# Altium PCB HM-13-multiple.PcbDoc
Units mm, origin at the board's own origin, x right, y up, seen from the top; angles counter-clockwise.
Board outline 81.48 x 88.14 mm, 2 copper layers (Top Layer, Bottom Layer); 96 components, 8 nets, 330 pads, 208 vias.
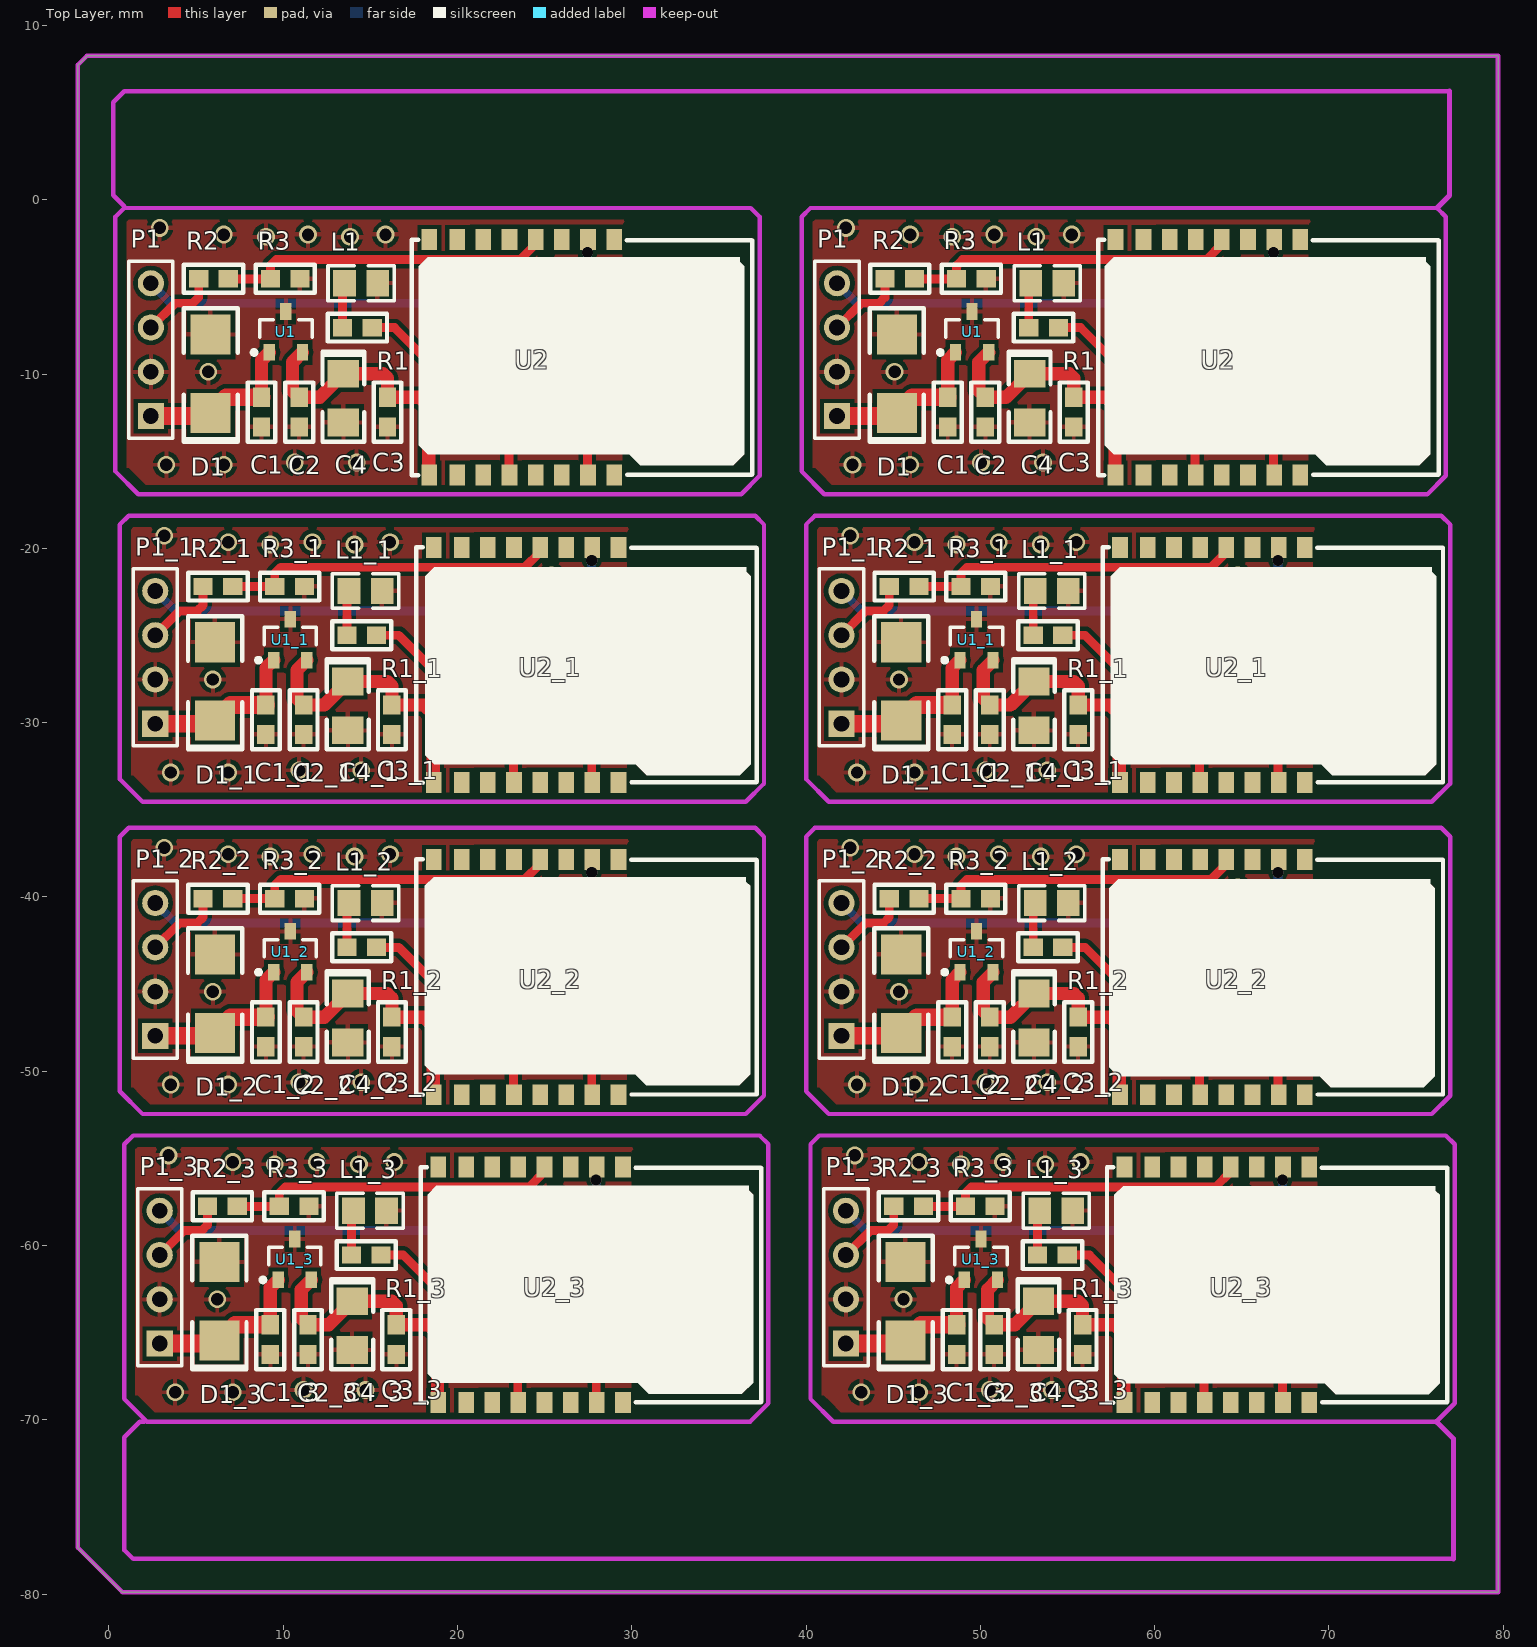
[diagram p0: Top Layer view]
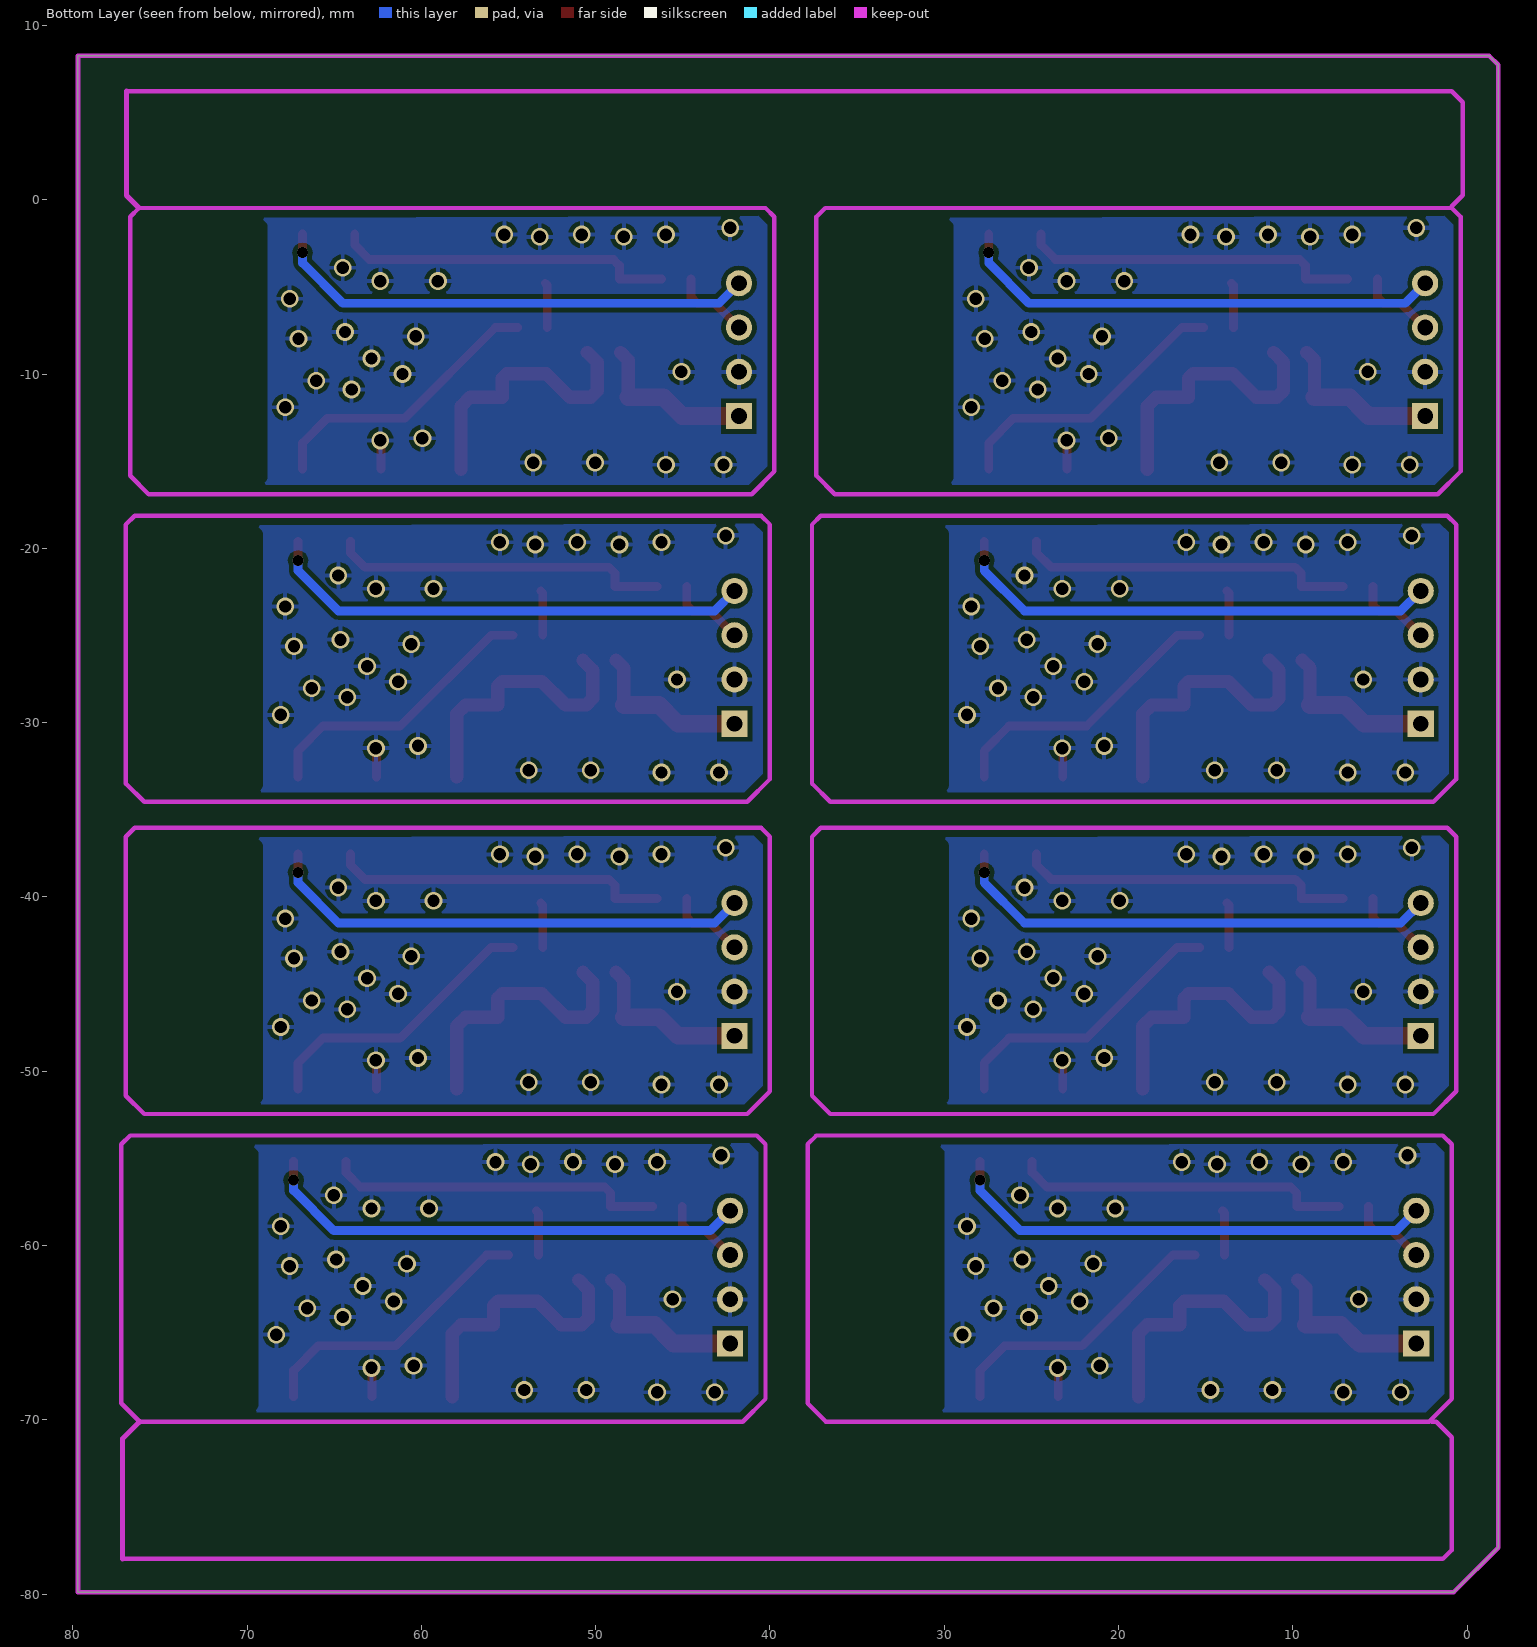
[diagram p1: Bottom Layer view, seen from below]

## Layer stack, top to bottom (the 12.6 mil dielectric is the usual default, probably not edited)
Top Solder: solder mask 0.0102, Solder Resist, Dk 3.5
Top Layer: signal copper 0.0356
Dielectric 1: dielectric 0.32, FR-4, Dk 4.8
Bottom Layer: signal copper 0.0356
Bottom Solder: solder mask 0.0102, Solder Resist, Dk 3.5

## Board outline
-1.778,5.842 -1.778,7.747 -1.27,8.255 79.705,8.255 79.705,-79.883 0.762,-79.883 -1.778,-77.343

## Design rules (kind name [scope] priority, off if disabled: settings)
Clearance [All] p1: gap=0.254
PolygonConnect [All] p1: connectstyle=Relief reliefconductorwidth=0.254 reliefentries=4 polygonreliefangle="90 Angle" airgapwidth=0.254
RoutingVias [All] p1: holewidth=0.711 width=1.016 viastyle="Through Hole" minholewidth=0.635 minwidth=0.381 maxholewidth=0.711 maxwidth=1.016
SolderMaskExpansion [All] p1: expansion=0.102
Width [All] p1: maxlimit=1.016 minlimit=0.254 preferedwidth=0.508
30 further rules are at their usual default settings.

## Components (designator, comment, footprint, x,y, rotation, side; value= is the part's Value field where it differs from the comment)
C1 "1uF" 0603 8.767,-12.185 r90 top
C1 "1uF" 0603 48.137,-12.185 r90 top
C1_1 "1uF" 0603 48.391,-29.838 r90 top (schematic designator C1)
C1_1 "1uF" 0603 9.021,-29.838 r90 top (schematic designator C1)
C1_2 "1uF" 0603 48.391,-47.745 r90 top (schematic designator C1)
C1_2 "1uF" 0603 9.021,-47.745 r90 top (schematic designator C1)
C1_3 "1uF" 0603 48.645,-65.398 r90 top (schematic designator C1)
C1_3 "1uF" 0603 9.275,-65.398 r90 top (schematic designator C1)
C2 "1uF" 0603 10.926,-12.185 r90 top
C2 "1uF" 0603 50.296,-12.185 r90 top
C2_1 "1uF" 0603 50.55,-29.838 r90 top (schematic designator C2)
C2_1 "1uF" 0603 11.18,-29.838 r90 top (schematic designator C2)
C2_2 "1uF" 0603 50.55,-47.745 r90 top (schematic designator C2)
C2_2 "1uF" 0603 11.18,-47.745 r90 top (schematic designator C2)
C2_3 "1uF" 0603 50.804,-65.398 r90 top (schematic designator C2)
C2_3 "1uF" 0603 11.434,-65.398 r90 top (schematic designator C2)
C3 "0.1uF" 0603 15.996,-12.185 r90 top
C3 "0.1uF" 0603 55.366,-12.185 r90 top
C3_1 "0.1uF" 0603 55.62,-29.838 r90 top (schematic designator C3)
C3_1 "0.1uF" 0603 16.25,-29.838 r90 top (schematic designator C3)
C3_2 "0.1uF" 0603 55.62,-47.745 r90 top (schematic designator C3)
C3_2 "0.1uF" 0603 16.25,-47.745 r90 top (schematic designator C3)
C3_3 "0.1uF" 0603 55.874,-65.398 r90 top (schematic designator C3)
C3_3 "0.1uF" 0603 16.504,-65.398 r90 top (schematic designator C3)
C4 "10uF/16V" 1206 13.456,-11.395 r270 top
C4 "10uF/16V" 1206 52.826,-11.395 r270 top
C4_1 "10uF/16V" 1206 53.08,-29.048 r270 top (schematic designator C4)
C4_1 "10uF/16V" 1206 13.71,-29.048 r270 top (schematic designator C4)
C4_2 "10uF/16V" 1206 53.08,-46.955 r270 top (schematic designator C4)
C4_2 "10uF/16V" 1206 13.71,-46.955 r270 top (schematic designator C4)
C4_3 "10uF/16V" 1206 53.334,-64.608 r270 top (schematic designator C4)
C4_3 "10uF/16V" 1206 13.964,-64.608 r270 top (schematic designator C4)
D1 "TVS" DO214-AC 5.836,-9.985 r270 top
D1 "TVS" DO214-AC 45.206,-9.985 r270 top
D1_1 "TVS" DO214-AC 45.46,-27.638 r270 top (schematic designator D1)
D1_1 "TVS" DO214-AC 6.09,-27.638 r270 top (schematic designator D1)
D1_2 "TVS" DO214-AC 45.46,-45.545 r270 top (schematic designator D1)
D1_2 "TVS" DO214-AC 6.09,-45.545 r270 top (schematic designator D1)
D1_3 "TVS" DO214-AC 45.714,-63.198 r270 top (schematic designator D1)
D1_3 "TVS" DO214-AC 6.344,-63.198 r270 top (schematic designator D1)
L1 "LED" 0805 14.472,-4.791 r0 top
L1 "LED" 0805 53.842,-4.791 r0 top
L1_1 "LED" 0805 54.096,-22.444 r0 top (schematic designator L1)
L1_1 "LED" 0805 14.726,-22.444 r0 top (schematic designator L1)
L1_2 "LED" 0805 54.096,-40.351 r0 top (schematic designator L1)
L1_2 "LED" 0805 14.726,-40.351 r0 top (schematic designator L1)
L1_3 "LED" 0805 54.35,-58.004 r0 top (schematic designator L1)
L1_3 "LED" 0805 14.98,-58.004 r0 top (schematic designator L1)
P1 "Header 4" HDR1X4 2.407,-12.411 r90 top
P1 "Header 4" HDR1X4 41.777,-12.411 r90 top
P1_1 "Header 4" HDR1X4 42.031,-30.064 r90 top (schematic designator P1)
P1_1 "Header 4" HDR1X4 2.661,-30.064 r90 top (schematic designator P1)
P1_2 "Header 4" HDR1X4 42.031,-47.971 r90 top (schematic designator P1)
P1_2 "Header 4" HDR1X4 2.661,-47.971 r90 top (schematic designator P1)
P1_3 "Header 4" HDR1X4 42.285,-65.624 r90 top (schematic designator P1)
P1_3 "Header 4" HDR1X4 2.915,-65.624 r90 top (schematic designator P1)
R1 "470" 0603 14.257,-7.321 r180 top
R1 "470" 0603 53.627,-7.321 r180 top
R1_1 "470" 0603 53.881,-24.974 r180 top (schematic designator R1)
R1_1 "470" 0603 14.511,-24.974 r180 top (schematic designator R1)
R1_2 "470" 0603 53.881,-42.881 r180 top (schematic designator R1)
R1_2 "470" 0603 14.511,-42.881 r180 top (schematic designator R1)
R1_3 "470" 0603 54.135,-60.534 r180 top (schematic designator R1)
R1_3 "470" 0603 14.765,-60.534 r180 top (schematic designator R1)
R2 "2.2K" 0603 6.002,-4.527 r180 top
R2 "2.2K" 0603 45.372,-4.527 r180 top
R2_1 "2.2K" 0603 45.626,-22.18 r180 top (schematic designator R2)
R2_1 "2.2K" 0603 6.256,-22.18 r180 top (schematic designator R2)
R2_2 "2.2K" 0603 45.626,-40.087 r180 top (schematic designator R2)
R2_2 "2.2K" 0603 6.256,-40.087 r180 top (schematic designator R2)
R2_3 "2.2K" 0603 45.88,-57.74 r180 top (schematic designator R2)
R2_3 "2.2K" 0603 6.51,-57.74 r180 top (schematic designator R2)
R3 "4.7K" 0603 10.115,-4.527 r180 top
R3 "4.7K" 0603 49.485,-4.527 r180 top
R3_1 "4.7K" 0603 49.739,-22.18 r180 top (schematic designator R3)
R3_1 "4.7K" 0603 10.369,-22.18 r180 top (schematic designator R3)
R3_2 "4.7K" 0603 49.739,-40.087 r180 top (schematic designator R3)
R3_2 "4.7K" 0603 10.369,-40.087 r180 top (schematic designator R3)
R3_3 "4.7K" 0603 49.993,-57.74 r180 top (schematic designator R3)
R3_3 "4.7K" 0603 10.623,-57.74 r180 top (schematic designator R3)
U1 "AP7313" AP7313-33SAG-7 10.154,-7.585 r90 top
U1 "AP7313" AP7313-33SAG-7 49.524,-7.585 r90 top
U1_1 "AP7313" AP7313-33SAG-7 49.778,-25.238 r90 top (schematic designator U1)
U1_1 "AP7313" AP7313-33SAG-7 10.408,-25.238 r90 top (schematic designator U1)
U1_2 "AP7313" AP7313-33SAG-7 49.778,-43.145 r90 top (schematic designator U1)
U1_2 "AP7313" AP7313-33SAG-7 10.408,-43.145 r90 top (schematic designator U1)
U1_3 "AP7313" AP7313-33SAG-7 50.032,-60.798 r90 top (schematic designator U1)
U1_3 "AP7313" AP7313-33SAG-7 10.662,-60.798 r90 top (schematic designator U1)
U2 "HM-13" HM-13 17.387,-2.286 r270 top
U2 "HM-13" HM-13 56.757,-2.286 r270 top
U2_1 "HM-13" HM-13 57.011,-19.939 r270 top (schematic designator U2)
U2_1 "HM-13" HM-13 17.641,-19.939 r270 top (schematic designator U2)
U2_2 "HM-13" HM-13 57.011,-37.846 r270 top (schematic designator U2)
U2_2 "HM-13" HM-13 17.641,-37.846 r270 top (schematic designator U2)
U2_3 "HM-13" HM-13 57.265,-55.499 r270 top (schematic designator U2)
U2_3 "HM-13" HM-13 17.895,-55.499 r270 top (schematic designator U2)

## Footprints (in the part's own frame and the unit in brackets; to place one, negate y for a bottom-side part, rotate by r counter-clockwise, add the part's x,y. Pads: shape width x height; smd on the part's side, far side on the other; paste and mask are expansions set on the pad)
0603 [mm]
  rect 1.1x1 smd: 1(-0.85,0.01) 2(0.85,0.01)
  silkscreen extent -1.7,-0.79 1.7,0.81
0805 [mm]
  rect 1.3x1.5 smd: 1(-0.95,0) 2(0.95,0)
  silkscreen extent -1.9,-1 1.9,1
1206 [mm]
  rect 1.6x1.8 smd: 1(-1.41,0) 2(1.39,0)
  silkscreen extent -2.68,-1.2 2.49,1.2
AP7313-33SAG-7 [mm] "SOT23, 3-Leads, Body 2.90x2.40mm, Pitch 0.95mm, IPC Medium Density"
  rect 0.95x0.65 smd: 1(-1.175,0.95) 2(-1.175,-0.95) 3(1.175,0)
  silkscreen extent -1.3,-1.5 0.7,1.95
DO214-AC [mm]
  rect 2.3x2.3 smd: 1(-2.25,0) 2(2.25,0)
  silkscreen extent -3.75,-1.55 3.9,1.55
HDR1X4 [mm] "Connector; Header; 4 Position"
  rect 1.5x1.5 hole 0.9: 1(0,0)
  round 1.5 hole 0.9: 2(2.54,0) 3(5.08,0) 4(7.62,0)
  silkscreen extent -1.27,-1.27 8.89,1.27
HM-13 [mm]
  rect 1.2x0.9 smd: 1(0,11.6) 2(0,10.1) 3(0,8.6) 4(0,7.1) 5(0,5.6) 6(0,4.1) 7(0,2.6) 8(0,1) 9(13.5,1) 10(13.5,2.6) 11(13.5,4.1) 12(13.5,5.6) 13(13.5,7.1) 14(13.5,8.6) 15(13.5,10.1) 16(13.5,11.6)
  silkscreen extent 0,0 13.51,19.53

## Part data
C1 C1 C1_1 C1_1 C1_2 C1_2 C1_3 C1_3 C2 C2 C2_1 C2_1 C2_2 C2_2 C2_3 C2_3 C3 C3 C3_1 C3_1 C3_2 C3_2 C3_3 C3_3: library part Cap1, "ceramic"
C4 C4 C4_1 C4_1 C4_2 C4_2 C4_3 C4_3: library part Cap3, "aluminum"
D1 D1 D1_1 D1_1 D1_2 D1_2 D1_3 D1_3: library part 6V8A-TVS
P1 P1 P1_1 P1_1 P1_2 P1_2 P1_3 P1_3: "Header, 4-Pin"
R1 R1 R1_1 R1_1 R1_2 R1_2 R1_3 R1_3 R2 R2 R2_1 R2_1 R2_2 R2_2 R2_3 R2_3 R3 R3 R3_1 R3_1 R3_2 R3_2 R3_3 R3_3: library part Res
U1 U1 U1_1 U1_1 U1_2 U1_2 U1_3 U1_3: library part AP7313-33SAG-7

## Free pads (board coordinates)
  round 2.032 on Keep-Out: 2(3.81,3.937) 4(74.371,-76.073)

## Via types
v1: diameter 1.016, hole 0.711, Top Layer to Bottom Layer, 200 vias
v2: diameter 0.635, hole 0.635, Top Layer to Bottom Layer, 8 vias

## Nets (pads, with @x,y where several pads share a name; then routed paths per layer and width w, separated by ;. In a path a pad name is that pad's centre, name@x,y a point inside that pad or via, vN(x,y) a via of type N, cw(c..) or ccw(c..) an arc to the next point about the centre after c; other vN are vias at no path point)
3.3V: C2.2@10.916,-11.335 C3.2@15.986,-11.335 C4.1@13.456,-9.985 U1.2@11.104,-8.76 U2.9@18.387,-15.786 | length 16
  Top Layer w0.762: U1.2@11.104,-8.76 10.535,-9.329 10.535,-10.954 10.916,-11.335 12.106,-11.335 13.456,-9.985 15.729,-9.985 15.986,-10.242 15.986,-11.335 17.841,-11.335 18.35,-11.844 U2.9@18.35,-15.459
5V: C1.2@8.757,-11.335 D1.2@5.836,-12.234 P1.1@2.407,-12.411 U1.1@9.204,-8.76 | length 9.6
  Top Layer w0.762: C1.2@8.757,-11.335 8.757,-9.207 U1.1@9.204,-8.76
  Top Layer w1.016: P1.1@2.407,-12.411 5.66,-12.411 5.836,-12.234 6.736,-11.335 C1.2@8.757,-11.335
GND: C1.1@8.757,-13.035 C2.1@10.916,-13.035 C3.1@15.986,-13.035 C4.2@13.456,-12.785 D1.1@5.836,-7.735 L1.2@15.422,-4.791 P1.2@2.407,-9.871 R3.1@10.965,-4.537 U1.3@10.154,-6.41 U2.12@22.987,-15.786 | length 1.7
  Top Layer w0.508: U2.12@22.95,-15.459 22.95,-13.839 v1(22.981,-13.808)
  other v1: 3.296,-15.205 6.598,-15.205 10.662,-15.078 14.218,-15.078 20.568,-13.681 28.442,-11.903 24.632,-10.887 26.664,-10.379 21.711,-9.998 5.709,-9.871 23.489,-9.109 27.68,-7.966 20.949,-7.839 25.013,-7.585 28.188,-5.68 19.679,-4.664 22.981,-4.664 25.14,-3.902 9.011,-2.124 13.837,-2.124 6.598,-1.997 11.424,-1.997 15.869,-1.997 2.915,-1.616
NetL1_1: L1.1@13.522,-4.791 R1.2@13.407,-7.331 | length 2.6
  Top Layer w0.508: R1.2@13.407,-7.331 13.407,-4.906 L1.1@13.522,-4.791
NetR1_1: R1.1@15.107,-7.331 U2.15@27.487,-15.786 | length 16.6
  Top Layer w0.508: R1.1@15.107,-7.331 16.377,-7.331 21.584,-12.538 26.029,-12.538 27.45,-13.959 U2.15@27.45,-15.459
NetR2_1: R2.1@6.852,-4.537 R3.2@9.265,-4.537 U2.4@24.487,-2.286 | length 19.5
  Top Layer w0.508: R2.1@6.852,-4.537 9.265,-4.537 9.265,-3.775 9.611,-3.429 23.612,-3.429 24.45,-2.591 U2.4@24.45,-1.959
RX: P1.3@2.407,-7.331 R2.2@5.152,-4.537 | length 4.5
  Top Layer w0.508: P1.3@2.407,-7.331 3.804,-5.934 4.82,-5.934 5.152,-5.602 R2.2@5.152,-4.537
TX: P1.4@2.407,-4.791 U2.2@27.487,-2.286 | length 28.1
  Top Layer w0.508: v2(27.45,-3.037) U2.2@27.45,-1.959
  Bottom Layer w0.508: P1.4@2.407,-4.791 3.55,-5.934 25.14,-5.934 27.45,-3.624 v2(27.45,-3.037)
pads on no net: C1.1@48.127,-13.035 C1.2@48.127,-11.335 C1_1.1 C1_1.2 C1_2.1 C1_2.2 C1_3.1 C1_3.2 C2.1@50.286,-13.035 C2.2@50.286,-11.335 C2_1.1 C2_1.2 C2_2.1 C2_2.2 C2_3.1 C2_3.2 C3.1@55.356,-13.035 C3.2@55.356,-11.335 C3_1.1 C3_1.2 C3_2.1 C3_2.2 C3_3.1 C3_3.2 C4.1@52.826,-9.985 C4.2@52.826,-12.785 C4_1.1 C4_1.2 C4_2.1 C4_2.2 C4_3.1 C4_3.2 D1.1@45.206,-7.735 D1.2@45.206,-12.234 D1_1.1 D1_1.2 D1_2.1 D1_2.2 D1_3.1 D1_3.2 L1.1@52.892,-4.791 L1.2@54.792,-4.791 L1_1.1 L1_1.2 L1_2.1 L1_2.2 L1_3.1 L1_3.2 P1.1@41.777,-12.411 P1.2@41.777,-9.871 P1.3@41.777,-7.331 P1.4@41.777,-4.791 P1_1.1 P1_1.2 P1_1.3 P1_1.4 P1_2.1 P1_2.2 P1_2.3 P1_2.4 P1_3.1 P1_3.2 P1_3.3 P1_3.4 R1.1@54.477,-7.331 R1.2@52.777,-7.331 R1_1.1 R1_1.2 R1_2.1 R1_2.2 R1_3.1 R1_3.2 R2.1@46.222,-4.537 R2.2@44.522,-4.537 R2_1.1 R2_1.2 R2_2.1 R2_2.2 R2_3.1 R2_3.2 R3.1@50.335,-4.537 R3.2@48.635,-4.537 R3_1.1 R3_1.2 R3_2.1 R3_2.2 R3_3.1 R3_3.2 U1.1@48.574,-8.76 U1.2@50.474,-8.76 U1.3@49.524,-6.41 U1_1.1 U1_1.2 U1_1.3 U1_2.1 U1_2.2 U1_2.3 U1_3.1 U1_3.2 U1_3.3 U2.1 U2.2@66.857,-2.286 U2.3 U2.4@63.857,-2.286 U2.5 U2.6 U2.7 U2.8 U2.9@57.757,-15.786 U2.10 U2.11 U2.12@62.357,-15.786 U2.13 U2.14 U2.15@66.857,-15.786 U2.16 U2_1.1 U2_1.2 U2_1.3 U2_1.4 U2_1.5 U2_1.6 U2_1.7 U2_1.8 U2_1.9 U2_1.10 U2_1.11 U2_1.12 U2_1.13 U2_1.14 U2_1.15 U2_1.16 U2_2.1 U2_2.2 U2_2.3 U2_2.4 U2_2.5 U2_2.6 U2_2.7 U2_2.8 U2_2.9 U2_2.10 U2_2.11 U2_2.12 U2_2.13 U2_2.14 U2_2.15 U2_2.16 U2_3.1 U2_3.2 U2_3.3 U2_3.4 U2_3.5 U2_3.6 U2_3.7 U2_3.8 U2_3.9 U2_3.10 U2_3.11 U2_3.12 U2_3.13 U2_3.14 U2_3.15 U2_3.16
copper on no net: | length 689.7
  Top Layer w0.508: 2.661,-42.891 4.058,-41.494 5.074,-41.494 5.406,-41.162 5.406,-40.097 ; 2.661,-24.984 4.058,-23.587 5.074,-23.587 5.406,-23.255 5.406,-22.19 ; 2.915,-60.544 4.312,-59.147 5.328,-59.147 5.66,-58.815 5.66,-57.75 ; 7.106,-40.097 9.519,-40.097 9.519,-39.335 9.865,-38.989 23.866,-38.989 24.704,-38.151 24.704,-37.519 ; 7.106,-22.19 9.519,-22.19 9.519,-21.428 9.865,-21.082 23.866,-21.082 24.704,-20.244 24.704,-19.612 ; 7.36,-57.75 9.773,-57.75 9.773,-56.988 10.119,-56.642 24.12,-56.642 24.958,-55.804 24.958,-55.172 ; 13.661,-42.891 13.661,-40.466 13.776,-40.351 ; 13.661,-24.984 13.661,-22.559 13.776,-22.444 ; 13.915,-60.544 13.915,-58.119 14.03,-58.004 ; 15.361,-42.891 16.631,-42.891 21.838,-48.098 26.283,-48.098 27.704,-49.519 27.704,-51.019 ; 15.361,-24.984 16.631,-24.984 21.838,-30.191 26.283,-30.191 27.704,-31.612 27.704,-33.112 ; 15.615,-60.544 16.885,-60.544 22.092,-65.751 26.537,-65.751 27.958,-67.172 27.958,-68.672 ; 23.204,-51.019 23.204,-49.399 v1(23.235,-49.368) ; 23.204,-33.112 23.204,-31.492 v1(23.235,-31.461) ; 23.458,-68.672 23.458,-67.052 v1(23.489,-67.021) ; v2(27.704,-38.597) 27.704,-37.519 ; v2(27.704,-20.69) 27.704,-19.612 ; v2(27.958,-56.25) 27.958,-55.172 ; 41.777,-7.331 43.174,-5.934 44.19,-5.934 44.522,-5.602 44.522,-4.537 ; 42.031,-42.891 43.428,-41.494 44.444,-41.494 44.776,-41.162 44.776,-40.097 ; 42.031,-24.984 43.428,-23.587 44.444,-23.587 44.776,-23.255 44.776,-22.19 ; 42.285,-60.544 43.682,-59.147 44.698,-59.147 45.03,-58.815 45.03,-57.75 ; 46.222,-4.537 48.635,-4.537 48.635,-3.775 48.981,-3.429 62.982,-3.429 63.82,-2.591 63.82,-1.959 ; 46.476,-40.097 48.889,-40.097 48.889,-39.335 49.235,-38.989 63.236,-38.989 64.074,-38.151 64.074,-37.519 ; 46.476,-22.19 48.889,-22.19 48.889,-21.428 49.235,-21.082 63.236,-21.082 64.074,-20.244 64.074,-19.612 ; 46.73,-57.75 49.143,-57.75 49.143,-56.988 49.489,-56.642 63.49,-56.642 64.328,-55.804 64.328,-55.172 ; 52.777,-7.331 52.777,-4.906 52.892,-4.791 ; 53.031,-42.891 53.031,-40.466 53.146,-40.351 ; 53.031,-24.984 53.031,-22.559 53.146,-22.444 ; 53.285,-60.544 53.285,-58.119 53.4,-58.004 ; 54.477,-7.331 55.747,-7.331 60.954,-12.538 65.399,-12.538 66.82,-13.959 66.82,-15.459 ; 54.731,-42.891 56.001,-42.891 61.208,-48.098 65.653,-48.098 67.074,-49.519 67.074,-51.019 ; 54.731,-24.984 56.001,-24.984 61.208,-30.191 65.653,-30.191 67.074,-31.612 67.074,-33.112 ; 54.985,-60.544 56.255,-60.544 61.462,-65.751 65.907,-65.751 67.328,-67.172 67.328,-68.672 ; 62.32,-15.459 62.32,-13.839 v1(62.351,-13.808) ; 62.574,-51.019 62.574,-49.399 v1(62.605,-49.368) ; 62.574,-33.112 62.574,-31.492 v1(62.605,-31.461) ; 62.828,-68.672 62.828,-67.052 v1(62.859,-67.021) ; v2(66.82,-3.037) 66.82,-1.959 ; v2(67.074,-38.597) 67.074,-37.519 ; v2(67.074,-20.69) 67.074,-19.612 ; v2(67.328,-56.25) 67.328,-55.172
  Top Layer w0.762: 9.011,-46.895 9.011,-44.767 9.458,-44.32 ; 9.011,-28.988 9.011,-26.86 9.458,-26.413 ; 9.265,-64.548 9.265,-62.42 9.712,-61.973 ; 11.358,-44.32 10.789,-44.889 10.789,-46.514 11.17,-46.895 12.36,-46.895 13.71,-45.545 15.983,-45.545 16.24,-45.802 16.24,-46.895 18.095,-46.895 18.604,-47.404 18.604,-51.019 ; 11.358,-26.413 10.789,-26.982 10.789,-28.607 11.17,-28.988 12.36,-28.988 13.71,-27.638 15.983,-27.638 16.24,-27.895 16.24,-28.988 18.095,-28.988 18.604,-29.497 18.604,-33.112 ; 11.612,-61.973 11.043,-62.542 11.043,-64.167 11.424,-64.548 12.614,-64.548 13.964,-63.198 16.237,-63.198 16.494,-63.455 16.494,-64.548 18.349,-64.548 18.858,-65.057 18.858,-68.672 ; 48.127,-11.335 48.127,-9.207 48.574,-8.76 ; 48.381,-46.895 48.381,-44.767 48.828,-44.32 ; 48.381,-28.988 48.381,-26.86 48.828,-26.413 ; 48.635,-64.548 48.635,-62.42 49.082,-61.973 ; 50.474,-8.76 49.905,-9.329 49.905,-10.954 50.286,-11.335 51.476,-11.335 52.826,-9.985 55.099,-9.985 55.356,-10.242 55.356,-11.335 57.211,-11.335 57.72,-11.844 57.72,-15.459 ; 50.728,-44.32 50.159,-44.889 50.159,-46.514 50.54,-46.895 51.73,-46.895 53.08,-45.545 55.353,-45.545 55.61,-45.802 55.61,-46.895 57.465,-46.895 57.974,-47.404 57.974,-51.019 ; 50.728,-26.413 50.159,-26.982 50.159,-28.607 50.54,-28.988 51.73,-28.988 53.08,-27.638 55.353,-27.638 55.61,-27.895 55.61,-28.988 57.465,-28.988 57.974,-29.497 57.974,-33.112 ; 50.982,-61.973 50.413,-62.542 50.413,-64.167 50.794,-64.548 51.984,-64.548 53.334,-63.198 55.607,-63.198 55.864,-63.455 55.864,-64.548 57.719,-64.548 58.228,-65.057 58.228,-68.672
  Top Layer w1.016: 2.661,-47.971 5.914,-47.971 6.09,-47.794 6.99,-46.895 9.011,-46.895 ; 2.661,-30.064 5.914,-30.064 6.09,-29.887 6.99,-28.988 9.011,-28.988 ; 2.915,-65.624 6.168,-65.624 6.344,-65.447 7.244,-64.548 9.265,-64.548 ; 41.777,-12.411 45.03,-12.411 45.206,-12.234 46.106,-11.335 48.127,-11.335 ; 42.031,-47.971 45.284,-47.971 45.46,-47.794 46.36,-46.895 48.381,-46.895 ; 42.031,-30.064 45.284,-30.064 45.46,-29.887 46.36,-28.988 48.381,-28.988 ; 42.285,-65.624 45.538,-65.624 45.714,-65.447 46.614,-64.548 48.635,-64.548
  Bottom Layer w0.508: 2.661,-40.351 3.804,-41.494 25.394,-41.494 27.704,-39.184 v2(27.704,-38.597) ; 2.661,-22.444 3.804,-23.587 25.394,-23.587 27.704,-21.277 v2(27.704,-20.69) ; 2.915,-58.004 4.058,-59.147 25.648,-59.147 27.958,-56.837 v2(27.958,-56.25) ; 41.777,-4.791 42.92,-5.934 64.51,-5.934 66.82,-3.624 v2(66.82,-3.037) ; 42.031,-40.351 43.174,-41.494 64.764,-41.494 67.074,-39.184 v2(67.074,-38.597) ; 42.031,-22.444 43.174,-23.587 64.764,-23.587 67.074,-21.277 v2(67.074,-20.69) ; 42.285,-58.004 43.428,-59.147 65.018,-59.147 67.328,-56.837 v2(67.328,-56.25)
  other v1: 3.804,-68.418 7.106,-68.418 43.174,-68.418 46.476,-68.418 11.17,-68.291 14.726,-68.291 50.54,-68.291 54.096,-68.291 21.076,-66.894 60.446,-66.894 28.95,-65.116 68.32,-65.116 25.14,-64.1 64.51,-64.1 27.172,-63.592 66.542,-63.592 22.219,-63.211 61.589,-63.211 6.217,-63.084 45.587,-63.084 23.997,-62.322 63.367,-62.322 28.188,-61.179 67.558,-61.179 21.457,-61.052 60.827,-61.052 25.521,-60.798 64.891,-60.798 28.696,-58.893 68.066,-58.893 20.187,-57.877 23.489,-57.877 59.557,-57.877 62.859,-57.877 25.648,-57.115 65.018,-57.115 9.519,-55.337 14.345,-55.337 48.889,-55.337 53.715,-55.337 7.106,-55.21 11.932,-55.21 16.377,-55.21 46.476,-55.21 51.302,-55.21 55.747,-55.21 3.423,-54.829 42.793,-54.829 3.55,-50.765 6.852,-50.765 42.92,-50.765 46.222,-50.765 10.916,-50.638 14.472,-50.638 50.286,-50.638 53.842,-50.638 20.822,-49.241 60.192,-49.241 28.696,-47.463 68.066,-47.463 24.886,-46.447 64.256,-46.447 26.918,-45.939 66.288,-45.939 21.965,-45.558 61.335,-45.558 5.963,-45.431 45.333,-45.431 23.743,-44.669 63.113,-44.669 27.934,-43.526 67.304,-43.526 21.203,-43.399 60.573,-43.399 25.267,-43.145 64.637,-43.145 28.442,-41.24 67.812,-41.24 19.933,-40.224 23.235,-40.224 59.303,-40.224 62.605,-40.224 25.394,-39.462 64.764,-39.462 9.265,-37.684 14.091,-37.684 48.635,-37.684 53.461,-37.684 6.852,-37.557 11.678,-37.557 16.123,-37.557 46.222,-37.557 51.048,-37.557 55.493,-37.557 3.169,-37.176 42.539,-37.176 3.55,-32.858 6.852,-32.858 42.92,-32.858 46.222,-32.858 10.916,-32.731 14.472,-32.731 50.286,-32.731 53.842,-32.731 20.822,-31.334 60.192,-31.334 28.696,-29.556 68.066,-29.556 24.886,-28.54 64.256,-28.54 26.918,-28.032 66.288,-28.032 21.965,-27.651 61.335,-27.651 5.963,-27.524 45.333,-27.524 23.743,-26.762 63.113,-26.762 27.934,-25.619 67.304,-25.619 21.203,-25.492 60.573,-25.492 25.267,-25.238 64.637,-25.238 28.442,-23.333 67.812,-23.333 19.933,-22.317 23.235,-22.317 59.303,-22.317 62.605,-22.317 25.394,-21.555 64.764,-21.555 9.265,-19.777 14.091,-19.777 48.635,-19.777 53.461,-19.777 6.852,-19.65 11.678,-19.65 16.123,-19.65 46.222,-19.65 51.048,-19.65 55.493,-19.65 3.169,-19.269 42.539,-19.269 42.666,-15.205 45.968,-15.205 50.032,-15.078 53.588,-15.078 59.938,-13.681 67.812,-11.903 64.002,-10.887 66.034,-10.379 61.081,-9.998 45.079,-9.871 62.859,-9.109 67.05,-7.966 60.319,-7.839 64.383,-7.585 67.558,-5.68 59.049,-4.664 62.351,-4.664 64.51,-3.902 48.381,-2.124 53.207,-2.124 45.968,-1.997 50.794,-1.997 55.239,-1.997 42.285,-1.616

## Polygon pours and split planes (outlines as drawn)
GND on Bottom Layer "GND" (solid, pour order 52): 30.257,-1.019 36.607,-1.019 36.988,-1.4 36.988,-15.624 36.226,-16.386 30.13,-16.386 30.094,-16.422 1.942,-16.422 0.926,-15.406 0.799,-15.279 0.799,-5.119 0.799,-1.436 1.307,-0.928
no net on Bottom Layer "GND" (solid, pour order 96): 69.627,-1.019 75.977,-1.019 76.358,-1.4 76.358,-15.624 75.596,-16.386 69.5,-16.386 69.464,-16.422 41.312,-16.422 40.296,-15.406 40.169,-15.279 40.169,-5.119 40.169,-1.436 40.677,-0.928
no net on Bottom Layer "GND" (solid, pour order 106): 69.881,-18.672 76.231,-18.672 76.612,-19.053 76.612,-33.277 75.85,-34.039 69.754,-34.039 69.718,-34.075 41.566,-34.075 40.55,-33.059 40.423,-32.932 40.423,-22.772 40.423,-19.089 40.931,-18.581
no net on Bottom Layer "GND" (solid, pour order 108): 30.511,-18.672 36.861,-18.672 37.242,-19.053 37.242,-33.277 36.48,-34.039 30.384,-34.039 30.348,-34.075 2.196,-34.075 1.18,-33.059 1.053,-32.932 1.053,-22.772 1.053,-19.089 1.561,-18.581
no net on Bottom Layer "GND" (solid, pour order 118): 69.881,-36.579 76.231,-36.579 76.612,-36.96 76.612,-51.184 75.85,-51.946 69.754,-51.946 69.718,-51.982 41.566,-51.982 40.55,-50.966 40.423,-50.839 40.423,-40.679 40.423,-36.996 40.931,-36.488
no net on Bottom Layer "GND" (solid, pour order 120): 30.511,-36.579 36.861,-36.579 37.242,-36.96 37.242,-51.184 36.48,-51.946 30.384,-51.946 30.348,-51.982 2.196,-51.982 1.18,-50.966 1.053,-50.839 1.053,-40.679 1.053,-36.996 1.561,-36.488
no net on Bottom Layer "GND" (solid, pour order 130): 70.135,-54.232 76.485,-54.232 76.866,-54.613 76.866,-68.837 76.104,-69.599 70.008,-69.599 69.972,-69.635 41.82,-69.635 40.804,-68.619 40.677,-68.492 40.677,-58.332 40.677,-54.649 41.185,-54.141
no net on Bottom Layer "GND" (solid, pour order 132): 30.765,-54.232 37.115,-54.232 37.496,-54.613 37.496,-68.837 36.734,-69.599 30.638,-69.599 30.602,-69.635 2.45,-69.635 1.434,-68.619 1.307,-68.492 1.307,-58.332 1.307,-54.649 1.815,-54.141
GND on Top Layer "GND" (solid, pour order 54): 1.016,-1.27 1.143,-1.143 36.408,-1.143 36.57,-0.981 36.957,-1.367 36.957,-1.905 36.957,-15.58 36.189,-16.348 30.093,-16.348 2.124,-16.348 1.524,-15.748 1.143,-15.367 1.016,-15.367
no net on Top Layer "GND" (solid, pour order 98): 40.386,-1.27 40.513,-1.143 75.778,-1.143 75.94,-0.981 76.327,-1.367 76.327,-1.905 76.327,-15.58 75.559,-16.348 69.463,-16.348 41.494,-16.348 40.894,-15.748 40.513,-15.367 40.386,-15.367
no net on Top Layer "GND" (solid, pour order 112): 40.64,-18.923 40.767,-18.796 76.032,-18.796 76.194,-18.634 76.581,-19.02 76.581,-19.558 76.581,-33.233 75.813,-34.001 69.717,-34.001 41.748,-34.001 41.148,-33.401 40.767,-33.02 40.64,-33.02
no net on Top Layer "GND" (solid, pour order 114): 1.27,-18.923 1.397,-18.796 36.662,-18.796 36.824,-18.634 37.211,-19.02 37.211,-19.558 37.211,-33.233 36.443,-34.001 30.347,-34.001 2.378,-34.001 1.778,-33.401 1.397,-33.02 1.27,-33.02
no net on Top Layer "GND" (solid, pour order 124): 40.64,-36.83 40.767,-36.703 76.032,-36.703 76.194,-36.541 76.581,-36.927 76.581,-37.465 76.581,-51.14 75.813,-51.908 69.717,-51.908 41.748,-51.908 41.148,-51.308 40.767,-50.927 40.64,-50.927
no net on Top Layer "GND" (solid, pour order 126): 1.27,-36.83 1.397,-36.703 36.662,-36.703 36.824,-36.541 37.211,-36.927 37.211,-37.465 37.211,-51.14 36.443,-51.908 30.347,-51.908 2.378,-51.908 1.778,-51.308 1.397,-50.927 1.27,-50.927
no net on Top Layer "GND" (solid, pour order 136): 40.894,-54.483 41.021,-54.356 76.286,-54.356 76.448,-54.194 76.835,-54.58 76.835,-55.118 76.835,-68.793 76.067,-69.561 69.971,-69.561 42.002,-69.561 41.402,-68.961 41.021,-68.58 40.894,-68.58
no net on Top Layer "GND" (solid, pour order 138): 1.524,-54.483 1.651,-54.356 36.916,-54.356 37.078,-54.194 37.465,-54.58 37.465,-55.118 37.465,-68.793 36.697,-69.561 30.601,-69.561 2.632,-69.561 2.032,-68.961 1.651,-68.58 1.524,-68.58

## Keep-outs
Keep-Out Layer:
  lines w0.254: 2.032,-70.104 1.778,-70.104 0.889,-70.993 0.889,-77.47 1.397,-77.978 77.14,-77.978 ; 37.332,-15.332 37.332,-0.981 36.824,-0.473 0.883,-0.473 ; 37.332,-15.078 37.332,-15.84 36.281,-16.891 1.681,-16.891 0.375,-15.586 0.375,-0.981 0.883,-0.473 ; 37.586,-50.892 37.586,-36.541 37.078,-36.033 1.137,-36.033 0.629,-36.541 0.629,-51.146 1.935,-52.451 36.535,-52.451 37.586,-51.4 37.586,-50.638 ; 37.586,-32.985 37.586,-18.634 37.078,-18.126 1.137,-18.126 0.629,-18.634 0.629,-33.239 1.935,-34.544 36.535,-34.544 37.586,-33.493 37.586,-32.731 ; 37.84,-68.545 37.84,-54.194 37.332,-53.686 1.391,-53.686 0.883,-54.194 0.883,-68.799 2.189,-70.104 36.789,-70.104 37.84,-69.053 37.84,-68.291 ; 76.702,-15.332 76.702,-0.981 76.194,-0.473 40.253,-0.473 39.745,-0.981 39.745,-15.586 41.051,-16.891 75.651,-16.891 76.702,-15.84 76.702,-15.078 ; 76.911,6.223 0.889,6.223 0.254,5.588 0.254,1.905 0.254,0.254 0.883,-0.375 0.883,-0.473 ; 76.956,-50.892 76.956,-36.541 76.448,-36.033 40.507,-36.033 39.999,-36.541 39.999,-51.146 41.305,-52.451 75.905,-52.451 76.956,-51.4 76.956,-50.638 ; 76.956,-32.985 76.956,-18.634 76.448,-18.126 40.507,-18.126 39.999,-18.634 39.999,-33.239 41.305,-34.544 75.905,-34.544 76.956,-33.493 76.956,-32.731 ; 77.21,-68.545 77.21,-54.194 76.702,-53.686 40.761,-53.686 40.253,-54.194 40.253,-68.799 41.559,-70.104 76.159,-70.104 77.21,-69.053 77.21,-68.291 ; 79.705,-79.883 0.762,-79.883 -1.778,-77.343 -1.778,5.842 -1.778,6.731 -1.778,7.747 -1.27,8.255 79.705,8.255
  lines w0.3: 76.159,-70.104 77.14,-71.085 77.14,-72.949 77.14,-77.978 ; 76.194,-0.473 76.911,0.245 76.911,2.057 76.911,6.223 ; 79.705,-79.883 79.705,8.255

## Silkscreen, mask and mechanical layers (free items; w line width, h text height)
Top Overlay:
  region: 17.78,-3.81 18.288,-3.302 36.195,-3.302 36.195,-3.556 36.449,-3.81 36.449,-14.605 35.814,-15.24 30.48,-15.24 29.845,-14.605 18.288,-14.605 17.78,-14.097
  region: 57.15,-3.81 57.658,-3.302 75.565,-3.302 75.565,-3.556 75.819,-3.81 75.819,-14.605 75.184,-15.24 69.85,-15.24 69.215,-14.605 57.658,-14.605 57.15,-14.097
  region: 18.161,-21.59 18.669,-21.082 36.576,-21.082 36.576,-21.336 36.83,-21.59 36.83,-32.385 36.195,-33.02 30.861,-33.02 30.226,-32.385 18.669,-32.385 18.161,-31.877
  region: 57.48,-21.59 57.988,-21.082 75.895,-21.082 75.895,-21.336 76.149,-21.59 76.149,-32.385 75.514,-33.02 70.18,-33.02 69.545,-32.385 57.988,-32.385 57.48,-31.877
  region: 18.136,-39.37 18.644,-38.862 36.551,-38.862 36.551,-39.116 36.805,-39.37 36.805,-50.165 36.17,-50.8 30.836,-50.8 30.201,-50.165 18.644,-50.165 18.136,-49.657
  region: 57.404,-39.497 57.912,-38.989 75.819,-38.989 75.819,-39.243 76.073,-39.497 76.073,-50.292 75.438,-50.927 70.104,-50.927 69.469,-50.292 57.912,-50.292 57.404,-49.784
  region: 57.683,-57.099 58.191,-56.591 76.098,-56.591 76.098,-56.845 76.352,-57.099 76.352,-67.894 75.717,-68.529 70.383,-68.529 69.748,-67.894 58.191,-67.894 57.683,-67.386
  region: 18.288,-57.074 18.796,-56.566 36.703,-56.566 36.703,-56.82 36.957,-57.074 36.957,-67.869 36.322,-68.504 30.988,-68.504 30.353,-67.869 18.796,-67.869 18.288,-67.361

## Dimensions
79.705,8.255 to -1.778,7.747 on Top Overlay
79.705,8.255 to 79.705,-79.883 on Top Overlay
